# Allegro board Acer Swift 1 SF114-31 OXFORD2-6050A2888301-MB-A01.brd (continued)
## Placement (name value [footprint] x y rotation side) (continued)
CN2002  ACER_50505_0044N_002_4P  [FPC_ACES_4_100_R_150]  107.23 82.85 270 bottom
CN2003  ACER_50505_0044N_002_4P  [FPC_ACES_4_100_R_150]  50.1 156.25 180 bottom
CN2401  ALLTOP_C107MK_9093D_L_9P  [USB3_OTOP_9_DIP_RV_S_100_186]  6.8 113.2 90 bottom
CN2403  SUYIN_020173GR004M59GZL_4P  [USB_SYN_4_RS_S_110_250]  15 150.05 0 bottom
CN3000  ACES_50203_03001_001_30P  [WTB_ACES_30_050_SMD_R_F_265_1]  74.78 154.45 0 bottom
CN3150  CONCRAFT_099A4AC19HBLBNF_19P  [HDMI_CONFT_19_RS_060_218]  4.98 132.7 90 bottom
CN6000  HR_A1255WR_S_05PNLNT1TS1R_5P  [BTB_JOINT_5_125_M_215]  23.28 142.2 0 bottom
CN6050  ACES_50299_00901_001_9P  [HL10BM-6012B0131110-001]  93.32 19.9 180 bottom
CN9100  ACES_50503_0104N_001_10P  [FPC_ACES_10_100_R_200_3]  70.37 8.2 0 top
D250  SFI_SFI0402ML120C_LF_SMD_2P  [DS_100X050X060_2_S2]  114.7 150.11 90 bottom
D251  SFI_SFI0402ML120C_LF_SMD_2P  [DS_100X050X060_2_S2]  113.79 150.11 90 bottom
D252  SFI_SFI0402ML120C_LF_SMD_2P  [DS_100X050X060_2_S2]  112.87 150.11 90 bottom
D253  SFI_SFI0402ML120C_LF_SMD_2P  [DS_100X050X060_2_S2]  111.96 150.11 90 bottom
D254  SFI_SFI0402ML120C_LF_SMD_2P  [DS_100X050X060_2_S2]  111.05 150.11 90 bottom
D255  SFI_SFI0402ML120C_LF_SMD_2P  [DS_100X050X060_2_S2]  110.13 150.11 90 bottom
D256  SFI_SFI0402ML120C_LF_SMD_2P  [DS_100X050X060_2_S2]  109.22 150.11 90 bottom
D257  SFI_SFI0402ML120C_LF_SMD_2P  [DS_100X050X060_2_S2]  108.3 150.11 90 bottom
D280  LITEON_L30ESDXVC3_2_DSOT23_3P  [DSOT23_290X130X150_3_095]  111.86 61.75 0 bottom
D281  LITEON_L30ESDXVC3_2_DSOT23_3P  [DSOT23_290X130X150_3_095]  101.17 74.4 90 bottom
D282  SFI_SFI0402ML120C_LF_SMD_2P_DY  [DS_100X050X060_2_S2]  105 63.02 180 bottom
D500  LITEON_L30ESDXVC3_2_DSOT23_3P  [DSOT23_290X130X150_3_095]  30.5 28.04 180 bottom
D501  AMC_AZ2015_01H_SOD523_2P_DY  [DSSOD523_120X080X070_2_150]  12.82 55.32 270 bottom
D600  LITEON_L30ESDXVC3_2_DSOT23_3P_DY  [DSOT23_290X130X150_3_095]  6.96 73.02 0 bottom
D901  SFI_SFI0402ML120C_LF_SMD_2P_DY  [DS_100X050X060_2_S2]  19.22 24.36 90 bottom
D902  SFI_SFI0402ML120C_LF_SMD_2P_DY  [DS_100X050X060_2_S2]  23.16 22.58 90 bottom
D2406  AMAZING_AZ1045_04F_R7G_10P  [DS_250X100X065_10_050]  19.04 113 90 bottom
D2409  AMC_AZC099_04S_R7G_SOT23_6P  [DSSOT23_290X160X145_6_095]  18.97 109.14 0 bottom
D2410  AMC_AZC099_04S_R7G_SOT23_6P  [DSSOT23_290X160X145_6_095]  28.52 153.76 180 top
D3000  AMC_AZC099_04S_R7G_SOT23_6P  [DSSOT23_290X160X145_6_095]  81.58 140.94 0 bottom
D3950  SFI_SFI0402_050E050PP_LF_SMD_2P  [DS_100X050X060_2_S2]  100.99 33.88 270 top
D3951  SFI_SFI0402_050E050PP_LF_SMD_2P  [DS_100X050X060_2_S2]  111.14 32.41 0 bottom
D4500  SFI_SFI0603_240E2R5PP_LF_2P_DY  [DS_160X080X090_2]  85.67 101.83 90 bottom
D4501  DIODE-BAT54-TAP-PHP  [DSSOT23_292X130X109_3_095]  79.93 63.22 270 bottom
D4700  DIODE-BAT54-TAP-PHP  [DSSOT23_292X130X109_3_095]  67.81 162.76 0 top
D4701  DIODE-BAT54-TAP-PHP  [DSSOT23_292X130X109_3_095]  65.63 151.68 0 top
D6000  BAT54C_30V_0.2A  [TSMI_3B]  59.53 19.35 0 bottom
D6001  BAT54C_30V_0.2A  [TSMI_3B]  67.13 24 0 bottom
D7000  DIODE-BAT54-TAP-PHP  [DSSOT23_292X130X109_3_095]  93.01 147.04 270 bottom
D7152  SFI_SFI0402ML120C_LF_SMD_2P  [DS_100X050X060_2_S2]  14.83 137.29 270 top
D7200  BAT54_30V_0.2A_DY  [TSOT23_290X130X110_3_096_P1]  33.83 34.52 180 bottom
D7501  SFI0402_050E3R0PP_LF  [DS_100X050X060_2_S2]  69.29 149.45 270 top
D7503  SFI0402_050E3R0PP_LF  [DS_100X050X060_2_S2]  68.92 151.13 90 top
D9100  LITEON_L30ESDXVC3_2_DSOT23_3P  [DSOT23_290X130X150_3_095]  73.71 6.31 0 bottom
D9128  EVL_19_223_ S2T1D _C30_2T_4P  [LED_EVERLI_V_D_160X150X060]  43.2 7.75 180 bottom
D9129  EVL_19_223_ S2T1D _C30_2T_4P  [LED_EVERLI_V_D_160X150X060]  58.56 3.2 180 bottom
D9150  SFI_SFI0402ML120C_LF_SMD_2P_DY  [DS_100X050X060_2_S2]  51.06 2.52 180 top
D60000  DIODE-BAT54-TAP-PHP  [DSSOT23_292X130X109_3_095]  106.85 112.37 180 bottom
D60002  BAT54C_30V_0.2A  [TSMI_3B]  56.16 20.7 270 bottom
D60003  BAV99  [DSSOT23_290X130X110_3_095-2]  55.72 30.68 270 bottom
FIX1  -  [FIX_MASK]  15.16 143.18 0 top
FIX2  -  [FIX_MASK]  15.08 32.74 0 top
FIX3  -  [FIX_MASK]  105.2 18.29 0 top
FIX4  -  [FIX_MASK]  114.96 157.07 0 top
FIX5  -  [FIX_MASK]  15.16 143.18 180 bottom
FIX6  -  [FIX_MASK]  13.2 3.56 180 bottom
FIX7  -  [FIX_MASK]  105.58 18.16 180 bottom
FIX8  -  [FIX_MASK]  98.6 142.7 180 bottom
FIX23  -  [FIX_MASK]  53.03 151.03 180 bottom
FIX24  -  [FIX_MASK]  27.84 154.14 180 bottom
FIX25  -  [FIX_MASK]  52.14 157.17 0 top
FIX26  -  [FIX_MASK]  25.37 156.93 0 top
FIX9113  -  [FIX_MASK]  77.16 3.17 180 bottom
FIX9114  -  [FIX_MASK]  77.3 3.21 0 top
FIX9115  -  [FIX_MASK]  58.82 10.5 180 bottom
FIX9116  -  [FIX_MASK]  66.68 2.25 0 top
FUSE3004  1A_32V  [FUSE_160X080X031_2]  95.16 151.3 0 top
JACK600  SINGA_2SJ3095_078111F_6P  [AUDIO_SIGAT_6_R_165_165]  13.77 98.4 90 bottom
L300  FBM_11_160808_121T  [EMIS_BLM11]  65.58 162.41 270 top
L2404  MCF12102G900-T  [CAESAR-6014B0247601-001]  22 109.2 180 bottom
L2406  MCF12102G900-T  [CAESAR-6014B0247601-001]  31.94 154.05 180 top
L2432  WCM_2012SHS_850T  [LS_200X120X140_4_080]  22.83 111.81 180 bottom
L2440  WCM_2012SHS_850T  [LS_200X120X140_4_080]  22 113.72 180 bottom
L6000  PCMB061H_4R7MS  [LS_660X660X180_2_570]  78.99 27.28 270 bottom
L6100  PCMB061H-2R2MS  [LS_660X660X180_2_540]  72.18 133.58 270 bottom
L6150  PCMB061H-1R0MS  [LS_660X660X180_2_605]  92.38 133.58 270 bottom
L6610  PCMB061H-R33MS  [LS_660X660X180_4]  89.04 81.48 180 bottom
L6710  PCMB061H-R33MS  [LS_660X660X180_4]  80.95 46.66 90 bottom
L7600  KC_FBMA_11_321611_121A60T  [LS_320X160X130_2]  26.24 134.31 270 bottom
L7601  KC_FBMA_11_321611_121A60T  [LS_320X160X130_2]  73.15 26.82 270 bottom
L60300  PCMB061H-1R0MS  [LS_660X660X180_2_605]  48.49 30.08 90 bottom
L60600  NRS5020T1R0N  [LS_500X500X200_2_340_P2]  93.27 118.97 90 bottom
L60900  PCMB061H_R47MS  [LS_660X660X180_2_605]  90.52 109.12 270 bottom
NOREF  -  []  8.71 146.95 90 top
NOREF#2  -  []  50.01 153.44 0 top
NOREF#3  -  [unnamed#2]  2.37 73.75 90 top
NOREF#4  -  []  32.77 5.64 180 top
NOREF#5  -  []  7.71 10.85 90 top
NOREF#6  -  [unnamed#3]  13.47 90.75 90 top
NOREF#7  -  []  75.78 13.15 180 top
NOREF#8  -  []  106.22 91.49 270 top
NOREF#9  -  []  21.69 33.45 90 top
NOREF#10  -  []  99.56 160.95 90 top
NOREF#11  -  []  111.6 107.57 270 top
NOREF#12  -  []  116.97 77.79 90 top
NOREF#13  -  []  7.62 38.65 90 top
NOREF#14  -  []  43.57 156.67 0 top
NOREF#15  -  [unnamed#3]  59.37 7.25 90 top
NOREF#16  -  [unnamed#3]  118.77 5 90 top
NOREF#17  -  [unnamed#2]  0 151.75 90 top
NOREF#18  -  []  36.04 185.32 0 top
NOREF#19  -  []  61.1 149.95 270 top
NOREF#20  -  []  119.77 129.43 90 top
NOREF#21  -  []  119.77 101.43 90 top
NOREF#22  -  [unnamed#4]  80.32 10.26 90 top
NOREF#23  -  []  58.6 146.95 90 top
NOREF#24  -  [unnamed#5]  118.49 11.86 90 top
NOREF#25  -  [unnamed#4]  56.5 152.25 90 top
NOREF#26  -  []  38.82 13.15 90 top
NOREF#27  -  []  87.47 13.14 180 top
NOREF#28  -  []  119.77 29.87 90 top
NOREF#29  -  []  119.77 157.45 90 top
NOREF#30  -  [unnamed#3]  3 156.45 90 top
NOREF#31  -  [unnamed#3]  111.58 46.25 90 top
NOREF#32  -  []  37.54 161.75 180 top
NOREF#33  -  []  1.37 72.43 270 top
NOREF#34  -  []  3.62 56.1 270 top
NOREF#35  -  []  71.23 1.14 0 top
NOREF#36  -  []  119.77 57.79 90 top
NOREF#37  -  []  84.17 6.04 180 top
NOREF#38  -  [unnamed#3]  114.98 30.75 90 top
NOREF#39  -  []  -4.41 -5.85 0 top
NOREF#40  -  [unnamed#2]  83.18 6.05 270 top
NOREF#41  -  []  -1 157.01 90 top
NOREF#42  -  [unnamed#3]  0 164.25 90 top
NOREF#43  -  []  102.95 13.15 180 top
NOREF#44  -  [unnamed#3]  0 5 90 top
NOREF#45  -  [unnamed#5]  6.55 166.57 90 top
NOREF#46  -  []  58.62 161.75 90 top
NOREF#47  -  []  63.79 5.65 90 bottom
PAD319  POWERPAD1x1m  [POWERPAD1X1M]  65 160.22 90 top
PAD500  POWERPAD1x1m  [POWERPAD1X1M]  15.19 72.36 180 top
PAD501  POWERPAD1x1m  [POWERPAD1X1M]  7.26 51.63 90 bottom
PAD502  POWERPAD1x1m  [POWERPAD1X1M]  15.26 79.78 180 top
PAD503  POWERPAD1x1m  [POWERPAD1X1M]  12.16 41.66 180 bottom
PAD2000  -  [POWERPAD_2_0610]  106.5 101.96 270 bottom
PAD3003  POWERPAD1x1m  [POWERPAD1X1M]  60.5 141.55 0 bottom
PAD4501  POWERPAD2x2M_DY  [POWERPAD2X2M_NP]  82.29 65.02 180 top
PAD6100  -  [POWERPAD_2_0610]  77.26 127.74 270 bottom
PAD6110  -  [POWERPAD_2_0610]  68.35 143.18 90 bottom
PAD6121  POWERPAD1x1m  [POWERPAD1X1M]  77.64 141.2 0 bottom
PAD6150  -  [POWERPAD_2_0610]  95.17 127.86 270 bottom
PAD6160  -  [POWERPAD_2_0610]  86.53 143.99 0 bottom
PAD6610  -  [POWERPAD_2_0610]  101.01 78.13 0 bottom
PAD6710  -  [POWERPAD_2_0610]  89.38 38.79 270 bottom
PAD7101  -  [POWERPAD_2_0610]  68.5 125.83 180 bottom
PAD7102  -  [POWERPAD_2_0610]  87.32 123.67 0 bottom
PAD7103  POWERPAD1x1m  [POWERPAD1X1M]  88.31 128.63 180 bottom
PAD7104  -  [POWERPAD_2_0610]  61.01 125.83 0 bottom
PAD60300  -  [POWERPAD_2_0610]  40.08 35.05 90 bottom
PAD60310  -  [POWERPAD_2_0610]  46.91 20.21 0 bottom
PAD60350  POWERPAD1x1m  [POWERPAD1X1M]  42.11 20.45 270 bottom
PAD60351  POWERPAD1x1m  [POWERPAD1X1M]  33.35 24.87 90 bottom
PAD60610  -  [POWERPAD_2_0610]  94.66 124.43 270 bottom
PAD60900  -  [POWERPAD_2_0610]  102.79 103.1 270 bottom
PAD60910  -  [POWERPAD_2_0610]  94.79 110.44 0 bottom
PAD61000  POWERPAD1x1m  [POWERPAD1X1M]  100.12 125.2 90 bottom
PAD61110  POWERPAD1x1m  [POWERPAD1X1M]  102.79 122.28 90 bottom
PAD61700  POWERPAD1x1m  [POWERPAD1X1M]  105.33 115.42 0 bottom
Q281  PM513BA  [TSOT23_292X130X120_3_095]  106.65 61.98 270 bottom
Q300  L2N7002WT1G  [TSSOT323_200X125X100_3_065]  78.28 145.41 90 bottom
Q310  RU1C001UNTCL  [UMT3F_200X125X100_3_065]  101.14 157.33 90 top
Q311  RU1C001UNTCL  [UMT3F_200X125X100_3_065]  106.73 155.17 0 top
Q1300  FDC638APZ_DY  [TSOT_290X160X110_6_095]  55.17 125.07 0 bottom
Q1302  L2N7002DW1T1G  [TSSC88_200X125X110_6_065-2]  26.92 128.04 180 bottom
Q3000  PM513BA  [TSOT23_292X130X120_3_095]  57.71 142.09 90 bottom
Q3001  L2N7002DW1T1G  [TSSC88_200X125X110_6_065-2]  56.82 138.28 90 bottom
Q3003  L2N7002WT1G  [TSSOT323_200X125X100_3_065]  97.6 156.82 90 top
Q3004  PM513BA  [TSOT23_292X130X120_3_095]  94.55 154.03 90 top
Q3006  LMBT3904LT1G  [TSSOT23_292X130X111_3_096]  59.99 133.71 0 bottom
Q3007  L2N7002WT1G  [TSSOT323_200X125X100_3_065]  61.57 130.61 90 bottom
Q3150  RU1C001UNTCL  [UMT3F_200X125X100_3_065]  18.92 125.02 180 bottom
Q3151  RU1C001UNTCL  [UMT3F_200X125X100_3_065]  21.36 125.02 180 bottom
Q3152  L2N7002WT1G  [TSSOT323_200X125X100_3_065]  19.25 128.22 270 bottom
Q3153  L2N7002WT1G  [TSSOT323_200X125X100_3_065]  23.75 125.22 0 bottom
Q3500  RU1C001UNTCL_DY  [UMT3F_200X125X100_3_065]  105.33 130.4 90 bottom
Q3501  RU1C001UNTCL_DY  [UMT3F_200X125X100_3_065]  112.7 130.91 270 bottom
Q3502  L2N7002WT1G_DY  [TSSOT323_200X125X100_3_065]  110.03 131.29 0 bottom
Q4505  L2N7002WT1G_DY  [TSSOT323_200X125X100_3_065]  73.86 110.26 90 bottom
Q4506  L2N7002DW1T1G  [TSSC88_200X125X110_6_065-2]  82.09 131.67 0 bottom
Q4513  RU1C001UNTCL  [UMT3F_200X125X100_3_065]  101.41 45.91 180 bottom
Q4516  RU1C001UNTCL  [UMT3F_200X125X100_3_065]  112.9 108.1 0 bottom
Q4517  RU1C001UNTCL  [UMT3F_200X125X100_3_065]  111.96 103.63 90 bottom
Q4524  L2N7002WT1G  [TSSOT323_200X125X100_3_065]  115.31 107.9 0 bottom
Q4525  L2N7002WT1G  [TSSOT323_200X125X100_3_065]  114.55 103.66 0 bottom
Q4714  L2N7002WT1G  [TSSOT323_200X125X100_3_065]  111.6 112.45 0 bottom
Q6000  AON7934  [TSMOS_300X300X080_8_065_T4]  73.63 30.83 180 bottom
Q6010  RQ3E100BNFU7TB  [MOSFET_300X300X112_8_065]  53.44 17.39 90 top
Q6011  RQ3E070BNFU7TB  [MOSFET_300X300X112_8_065]  58.55 17.47 270 top
Q6012  RQ3E100BNFU7TB  [MOSFET_300X300X112_8_065]  87.2 33.02 180 bottom
Q6610  FAIRCHILD_FDMS3669S  [TSMOS_500X600X110_8_127_T1]  96.35 82.04 180 bottom
Q6710  FAIR_FDMS3664S_8P  [TSMOS_500X600X110_8_127_T1]  87.13 44.21 180 bottom
Q7000  L2N7002WT1G  [TSSOT323_200X125X100_3_065]  96.06 147.04 180 bottom
Q7106  L2N7002WT1G  [TSSOT323_200X125X100_3_065]  115.26 117.73 270 bottom
Q7108  L2N7002WT1G  [TSSOT323_200X125X100_3_065]  115.26 115.19 270 bottom
Q7114  L2N7002WT1G  [TSSOT323_200X125X100_3_065]  113.97 112.45 0 bottom
Q7120  L2N7002WT1G  [TSSOT323_200X125X100_3_065]  98.85 147.04 180 bottom
Q7202  PM513BA  [TSOT23_292X130X120_3_095]  35.76 38.61 0 bottom
Q7214  L2N7002DW1T1G  [TSSC88_200X125X110_6_065-2]  65.12 34.66 90 bottom
Q60002  L2N7002DW1T1G  [TSSC88_200X125X110_6_065-2]  54.07 23.9 0 bottom
Q60003  L2N7002DW1T1G  [TSSC88_200X125X110_6_065-2]  54.9 27.88 270 bottom
R20  100K_5%_2  [RSC_100X050X040_2]  113.92 152.24 270 top
R28  200_5%_2  [RSC_100X050X040_2]  113.56 110.39 0 bottom
R29  200_5%_2  [RSC_100X050X040_2]  112.95 115.93 270 bottom
R35  10K_5%_2  [RSC_100X050X040_2]  76.12 42.62 90 bottom
R281  0_5%_2_DY  [RSC_100X050X040_2]  110.46 59.03 90 bottom
R282  0_5%_2_DY  [RSC_100X050X040_2]  113.23 59.03 90 bottom
R283  0_5%_2  [RSC_100X050X040_2]  111.4 59.03 90 bottom
R284  0_5%_2  [RSC_100X050X040_2]  112.32 59.03 90 bottom
R285  0_5%_2  [RSC_100X050X040_2]  101.62 70.76 90 bottom
R286  0_5%_2_DY  [RSC_100X050X040_2]  101.27 72.03 0 bottom
R301  10K_5%_2  [RSC_100X050X040_2]  108.55 157.3 0 top
R308  47K_5%_2  [RSC_100X050X040_2]  88.9 148.31 180 top
R309  47K_5%_2  [RSC_100X050X040_2]  88.9 149.2 180 top
R310  1K_5%_2  [RSC_100X050X040_2]  103.31 157.95 0 top
R311  10K_5%_2  [RSC_100X050X040_2]  107.24 152.37 270 top
R312  0_5%_2_DY  [RSC_100X050X040_2]  106.35 152.37 270 top
R313  0_5%_2_DY  [RSC_100X050X040_2]  89.33 150.47 270 top
R314  0_5%_2_DY  [RSC_100X050X040_2]  90.6 151.1 0 top
R316  1.8K_5%_2  [RSC_100X050X040_2]  87.42 164.34 180 top
R317  1.8K_5%_2  [RSC_100X050X040_2]  87.42 165.23 180 top
R318  2.2_5%_3  [RSC_160X080X080_2]  66.51 156.97 0 top
R320  100K_5%_2  [RSC_100X050X040_2]  108.55 158.2 180 top
R321  3.3K_5%_2  [RSC_100X050X040_2]  86.92 149.2 0 top
R322  3.3K_5%_2  [RSC_100X050X040_2]  86.92 148.31 0 top
R323  10K_5%_2  [RSC_100X050X040_2]  108.33 156.03 90 top
R324  100K_5%_2  [RSC_100X050X040_2]  78.38 147.04 180 bottom
R325  0_5%_2_DY  [RSC_100X050X040_2]  84.05 146.3 180 top
R332  10K_5%_2_DY  [RSC_100X050X040_2]  67.13 158.47 0 top
R333  100K_5%_2  [RSC_100X050X040_2]  81.96 144.65 180 top
R334  10K_5%_2  [RSC_100X050X040_2]  64.88 157.57 90 top
R340  33_5%_2  [RSC_100X050X040_2]  73.12 41.33 0 bottom
R341  33_5%_2  [RSC_100X050X040_2]  72.41 52.27 90 bottom
R342  33_5%_2  [RSC_100X050X040_2]  71.78 38.66 180 bottom
R343  33_5%_2  [RSC_100X050X040_2]  71.78 37.74 180 bottom
R346  100K_5%_2  [RSC_100X050X040_2]  65.17 164.39 270 top
R350  10K_5%_2  [RSC_100X050X040_2]  78.48 144.07 270 top
R351  18.7K_1%_2  [RSC_100X050X040_2]  65.27 151.18 0 bottom
R352  100K_1%_NTC  [RSC_100X050X055_2]  64.92 149.91 270 bottom
R390  10K_5%_2  [RSC_100X050X040_2]  68.46 152.74 180 top
R391  10K_5%_2_DY  [RSC_100X050X040_2]  68.01 151.13 90 top
R500  short_0603_25  [RSC_160X080X080_2_25_SHORT]  8.61 57.91 270 bottom
R501  20K_1%_2_DY  [RSC_100X050X040_2]  14.81 57.51 90 top
R502  200K_5%_2  [RSC_100X050X040_2]  16.58 57.51 90 top
R503  1K_5%_2_DY  [RSC_100X050X040_2]  18.36 55.6 270 top
R504  100K_5%_2  [RSC_100X050X040_2]  15.69 57.51 90 top
R505  1K_5%_2  [RSC_100X050X040_2]  19.05 57.23 270 top
R506  0_5%_2  [RSC_100X050X040_2]  17.52 51.59 0 top
R507  75_5%_2  [RSC_100X050X040_2]  17.52 53.36 0 top
R508  0_5%_3  [RSC_160X080X055_2]  17.83 43.54 90 bottom
R509  0_5%_3  [RSC_160X080X055_2]  16.68 43.54 90 bottom
R510  0_5%_3  [RSC_160X080X055_2]  14.4 43.54 90 bottom
R511  0_5%_3  [RSC_160X080X055_2]  15.54 43.54 90 bottom
R512  100_5%_2  [RSC_100X050X040_2]  17.09 50.57 180 top
R513  short_0603_25  [RSC_160X080X080_2_25_SHORT]  15.41 49.63 180 bottom
R514  short_0402_15  [RSC_100X050X040_2_15_SHORT]  16.68 59.66 0 top
R515  1K_5%_2  [RSC_100X050X040_2]  19.05 58.83 90 top
R520  short_0402_5  [RSC_100X050X040_2_SHORT]  19.05 60.43 90 top
R521  short_0402_5  [RSC_100X050X040_2_SHORT]  20.09 53.85 270 top
R531  100K_5%_2  [RSC_100X050X040_2]  9.7 58.39 90 top
R600  2.2K_5%_2  [RSC_100X050X040_2]  14.96 85.98 180 bottom
R601  2.2K_5%_2  [RSC_100X050X040_2]  7.16 83.79 0 bottom
R602  0_5%_2  [RSC_100X050X040_2]  14.96 86.87 0 bottom
R603  0_5%_2  [RSC_100X050X040_2]  5.51 83.79 0 bottom
R604  22_5%_2  [RSC_100X050X040_2]  6.12 80.85 90 bottom
R605  22_5%_2  [RSC_100X050X040_2]  7.26 80.87 90 bottom
R606  4.7K_5%_2  [RSC_100X050X040_2]  8.18 80.87 90 bottom
R607  4.7K_5%_2  [RSC_100X050X040_2]  5.2 80.85 90 bottom
R610  0_5%_2_DY  [RSC_100X050X040_2]  6.19 90.55 0 bottom
R704  short_0402_15  [RSC_100X050X040_2_15_SHORT]  80.82 67.67 0 top
R900  6.2K_1%_2  [RSC_100X050X040_2]  15.08 19.68 270 bottom
R901  0_5%_2  [RSC_100X050X040_2]  20.87 13.9 0 bottom
R1301  0_5%_5  [RSC_200X125X115_2]  55.93 128.75 0 bottom
R1302  0_5%_2_DY  [RSC_100X050X040_2]  39.93 132.18 180 top
R1306  0_5%_2  [RSC_100X050X040_2]  39.93 133.07 0 top
R1307  10K_5%_2  [RSC_100X050X040_2]  27.35 130.02 180 bottom
R2000  RSC_0402_DY  [RSC_100X050X040_2]  116.23 98.83 0 bottom
R2001  10K_5%_2  [RSC_100X050X040_2]  112.01 101.93 180 bottom
R2410  10K_5%_2  [RSC_100X050X040_2]  18.39 120.93 270 bottom
R3000  47K_5%_2  [RSC_100X050X040_2]  55.29 140.82 0 bottom
R3001  470K_5%_2  [RSC_100X050X040_2]  55.8 139.93 0 bottom
R3004  100_5%_2  [RSC_100X050X040_2]  57.45 139.93 180 bottom
R3005  short_0603_10  [RSC_160X080X080_2_SHORT]  81.07 136.83 90 bottom
R3006  47K_5%_2  [RSC_100X050X040_2]  60.63 128.63 90 bottom
R3007  4.7K_5%_2  [RSC_100X050X040_2]  61.52 128.63 90 bottom
R3010  100K_5%_2  [RSC_100X050X040_2]  58.85 138.66 90 bottom
R3011  100_5%_2  [RSC_100X050X040_2]  83.64 140.23 90 bottom
R3013  100_5%_2  [RSC_100X050X040_2]  112.9 152.25 270 top
R3016  100K_5%_2  [RSC_100X050X040_2]  70.66 149.07 90 bottom
R3017  100K_5%_2  [RSC_100X050X040_2]  67.61 149.28 180 bottom
R3020  10K_5%_2  [RSC_100X050X040_2]  104.01 156.15 90 top
R3021  100K_5%_2  [RSC_100X050X040_2]  98.35 155.22 0 top
R3025  2.2K_5%_2  [RSC_100X050X040_2]  58.9 136.14 270 bottom
R3029  short_0603_10  [RSC_160X080X080_2_SHORT]  82.27 136.83 90 bottom
R3030  100K_5%_2  [RSC_100X050X040_2]  100.9 151.13 180 top
R3060  150_5%_2_DY  [RSC_100X050X040_2]  71.57 149.07 270 bottom
R3061  0_5%_2  [RSC_100X050X040_2]  70.3 150.98 0 bottom
R3068  0_5%_3  [RSC_160X080X055_2]  99.39 153.21 180 top
R3069  0_5%_3_DY  [RSC_160X080X055_2]  101.97 152.47 180 top
R3150  100K_5%_2  [RSC_100X050X040_2]  16.66 140.08 90 top
R3152  2.2K_5%_2  [RSC_100X050X040_2]  16.2 138.45 90 top
R3153  2.2K_5%_2  [RSC_100X050X040_2]  16.2 136.83 270 top
R3154  1K_5%_2  [RSC_100X050X040_2]  14.83 139.09 270 top
R3157  619_1%_2  [RSC_100X050X040_2]  18.11 125.81 270 top
R3158  619_1%_2  [RSC_100X050X040_2]  18.11 127.43 90 top
R3159  619_1%_2  [RSC_100X050X040_2]  19.02 128.57 270 top
R3160  619_1%_2  [RSC_100X050X040_2]  19.02 130.2 90 top
R3161  619_1%_2  [RSC_100X050X040_2]  18.11 131.34 270 top
R3162  619_1%_2  [RSC_100X050X040_2]  18.11 132.97 90 top
R3163  619_1%_2  [RSC_100X050X040_2]  19 135.71 90 top
R3164  619_1%_2  [RSC_100X050X040_2]  19 134.09 270 top
R3167  120_1%_2  [RSC_100X050X040_2]  14.83 126.62 270 top
R3168  120_1%_2  [RSC_100X050X040_2]  15.77 129.39 270 top
R3169  120_1%_2  [RSC_100X050X040_2]  14.86 132.16 270 top
R3170  120_1%_2  [RSC_100X050X040_2]  15.74 134.9 270 top
R3171  10K_5%_2  [RSC_100X050X040_2]  24 123.16 0 bottom
R3178  2.2K_5%_2  [RSC_100X050X040_2]  21.26 123.16 180 bottom
R3179  2.2K_5%_2  [RSC_100X050X040_2]  18.92 123.16 180 bottom
R3180  short_0603_25  [RSC_160X080X080_2_25_SHORT]  16.46 126.06 180 top
R3181  short_0603_25  [RSC_160X080X080_2_25_SHORT]  16.46 127.18 180 top
R3182  short_0603_25  [RSC_160X080X080_2_25_SHORT]  17.4 128.83 180 top
R3183  short_0603_25  [RSC_160X080X080_2_25_SHORT]  17.4 129.95 180 top
R3184  short_0603_25  [RSC_160X080X080_2_25_SHORT]  16.48 131.6 180 top
R3185  short_0603_25  [RSC_160X080X080_2_25_SHORT]  16.48 132.71 180 top
R3186  short_0603_25  [RSC_160X080X080_2_25_SHORT]  17.37 134.34 180 top
R3187  short_0603_25  [RSC_160X080X080_2_25_SHORT]  17.37 135.46 180 top
R3503  0_5%_2_DY  [RSC_100X050X040_2]  105.84 121.51 0 bottom
R3504  0_5%_2_DY  [RSC_100X050X040_2]  105.84 123.8 0 bottom
R3505  0_5%_2_DY  [RSC_100X050X040_2]  105.84 125.96 0 bottom
R3506  0_5%_2_DY  [RSC_100X050X040_2]  105.84 127.74 0 bottom
R3507  0_5%_2_DY  [RSC_100X050X040_2]  105.84 125.07 0 bottom
R3509  0_5%_2_DY  [RSC_100X050X040_2]  109.47 118.72 90 bottom
R3510  0_5%_2_DY  [RSC_100X050X040_2]  105.84 120.62 0 bottom
R3511  10K_5%_2_DY  [RSC_100X050X040_2]  105.84 128.63 180 bottom
R3513  10K_5%_2_DY  [RSC_100X050X040_2]  105.84 119.74 180 bottom
R3514  10K_5%_2_DY  [RSC_100X050X040_2]  112.19 132.56 180 bottom
R3515  10K_5%_2_DY  [RSC_100X050X040_2]  108.38 132.05 270 bottom
R3516  2.2K_5%_2_DY  [RSC_100X050X040_2]  108.38 130.4 270 bottom
R3950  0_5%_2_DY  [RSC_100X050X040_2]  101.29 42.16 180 top
R3955  0_5%_2  [RSC_100X050X040_2]  103.48 41.81 90 top
R3962  0_5%_2  [RSC_100X050X040_2]  95.04 37.13 0 top
R3963  10K_5%_2_DY  [RSC_100X050X040_2]  102.56 41.81 270 top
R3964  0_5%_3  [RSC_160X080X055_2]  111.73 35.81 90 bottom
R3965  10K_5%_2_DY  [RSC_100X050X040_2]  100.94 40.77 90 top
R3966  0_5%_3  [RSC_160X080X055_2]  97.33 43.36 180 bottom
R4100  243_1%_2  [RSC_100X050X040_2]  70.16 113.41 90 bottom
R4101  243_1%_2  [RSC_100X050X040_2]  52.95 117.79 0 top
R4102  243_1%_2  [RSC_100X050X040_2]  24.86 93.03 0 bottom
R4103  243_1%_2  [RSC_100X050X040_2]  31.73 108.58 180 bottom
R4104  4.7K_1%_2  [RSC_100X050X040_2]  67.63 117.13 270 top
R4105  4.7K_1%_2  [RSC_100X050X040_2]  68.13 115.82 180 top
R4106  243_1%_2  [RSC_100X050X040_2]  70.16 111.76 270 bottom
R4107  243_1%_2  [RSC_100X050X040_2]  52.95 118.68 0 top
R4108  243_1%_2  [RSC_100X050X040_2]  24.86 93.92 0 bottom
R4109  243_1%_2  [RSC_100X050X040_2]  33.33 108.58 0 bottom
R4110  4.7K_1%_2  [RSC_100X050X040_2]  70.2 115.81 180 top
R4111  4.7K_1%_2  [RSC_100X050X040_2]  70.2 117.59 0 top
R4112  0_5%_2_DY  [RSC_100X050X040_2]  70.2 118.47 0 top
R4113  0_5%_2_DY  [RSC_100X050X040_2]  68.58 118.5 180 top
R4114  80.6_1%_2  [RSC_100X050X040_2]  48.29 96.92 0 top
R4115  80.6_1%_2  [RSC_100X050X040_2]  48.3 97.86 0 top
R4116  80.6_1%_2  [RSC_100X050X040_2]  47.57 103.34 0 top
R4117  80.6_1%_2  [RSC_100X050X040_2]  46.32 104.33 90 top
R4118  80.6_1%_2  [RSC_100X050X040_2]  48.59 102.27 0 top
R4119  80.6_1%_2  [RSC_100X050X040_2]  42.75 100.66 0 top
R4120  80.6_1%_2  [RSC_100X050X040_2]  47.14 100.83 270 top
R4121  80.6_1%_2  [RSC_100X050X040_2]  42.67 101.61 0 top
R4122  80.6_1%_2  [RSC_100X050X040_2]  44.06 97.89 0 top
R4123  80.6_1%_2  [RSC_100X050X040_2]  42.87 105.86 90 top
R4124  80.6_1%_2  [RSC_100X050X040_2]  44.16 105.78 90 top
R4125  80.6_1%_2  [RSC_100X050X040_2]  41.72 103.8 90 top
R4126  80.6_1%_2  [RSC_100X050X040_2]  44.2 108.31 180 top
R4127  80.6_1%_2  [RSC_100X050X040_2]  39.27 106.74 0 top
R4128  80.6_1%_2  [RSC_100X050X040_2]  41.06 106.65 90 top
R4129  80.6_1%_2  [RSC_100X050X040_2]  40.88 109.55 270 top
R4130  80.6_1%_2  [RSC_100X050X040_2]  38.68 107.63 0 top
R4131  80.6_1%_2  [RSC_100X050X040_2]  38.91 108.54 0 top
R4132  80.6_1%_2  [RSC_100X050X040_2]  36.9 111.38 270 top
R4133  80.6_1%_2  [RSC_100X050X040_2]  38.55 111.51 270 top
R4134  80.6_1%_2  [RSC_100X050X040_2]  37.66 109.26 90 top
R4135  80.6_1%_2  [RSC_100X050X040_2]  39.61 109.89 180 top
R4136  80.6_1%_2  [RSC_100X050X040_2]  42.08 107.84 90 top
R4137  80.6_1%_2  [RSC_100X050X040_2]  42.05 109.54 90 top
R4138  80.6_1%_2  [RSC_100X050X040_2]  46.13 100.96 270 top
R4139  80.6_1%_2  [RSC_100X050X040_2]  35.89 109.84 0 top
R4140  80.6_1%_2  [RSC_100X050X040_2]  39.59 111.15 270 top
R4141  80.6_1%_2  [RSC_100X050X040_2]  45.28 103.72 90 top
R4142  80.6_1%_2  [RSC_100X050X040_2]  43.28 99.68 0 top
R4143  80.6_1%_2  [RSC_100X050X040_2]  44.04 98.79 0 top
R4144  243_1%_2  [RSC_100X050X040_2]  42.61 47.67 270 bottom
R4145  80.6_1%_2  [RSC_100X050X040_2]  40.9 55.98 90 top
R4146  80.6_1%_2  [RSC_100X050X040_2]  45.5 58.14 270 top
R4147  80.6_1%_2  [RSC_100X050X040_2]  40.14 57.4 0 top
R4148  80.6_1%_2  [RSC_100X050X040_2]  41.56 59.56 90 top
R4149  80.6_1%_2  [RSC_100X050X040_2]  43.94 58.39 180 top
R4150  80.6_1%_2  [RSC_100X050X040_2]  43.92 59.33 0 top
R4151  243_1%_2  [RSC_100X050X040_2]  42.6 49.27 90 bottom
R4152  80.6_1%_2  [RSC_100X050X040_2]  43.8 60.83 0 top
R4153  80.6_1%_2  [RSC_100X050X040_2]  39.63 55.27 0 top
R4154  80.6_1%_2  [RSC_100X050X040_2]  36.91 54.23 0 top
R4155  80.6_1%_2  [RSC_100X050X040_2]  43.35 56.97 0 top
R4156  80.6_1%_2  [RSC_100X050X040_2]  41.33 53.82 270 top
R4157  80.6_1%_2  [RSC_100X050X040_2]  36.91 53.31 0 top
R4158  80.6_1%_2  [RSC_100X050X040_2]  38.49 52.65 270 top
R4159  80.6_1%_2  [RSC_100X050X040_2]  38.01 51.28 0 top
R4160  80.6_1%_2  [RSC_100X050X040_2]  35.64 52.4 0 top
R4161  80.6_1%_2  [RSC_100X050X040_2]  37.35 50.36 0 top
R4162  80.6_1%_2  [RSC_100X050X040_2]  34.72 49.13 0 top
R4163  80.6_1%_2  [RSC_100X050X040_2]  35.39 50.03 0 top
R4164  80.6_1%_2  [RSC_100X050X040_2]  34.15 48.1 0 top
R4165  80.6_1%_2  [RSC_100X050X040_2]  38.31 47.65 90 top
R4166  80.6_1%_2  [RSC_100X050X040_2]  39.45 53.23 270 top
R4167  80.6_1%_2  [RSC_100X050X040_2]  37.35 49.45 0 top
R4168  80.6_1%_2  [RSC_100X050X040_2]  41.81 56.87 90 top
R4169  80.6_1%_2  [RSC_100X050X040_2]  34.93 51.43 0 top
R4170  80.6_1%_2  [RSC_100X050X040_2]  36.84 48.31 0 top
R4171  80.6_1%_2  [RSC_100X050X040_2]  44.6 57.07 270 top
R4172  4.7K_1%_2  [RSC_100X050X040_2]  47.65 40.23 180 top
R4173  0_5%_2_DY  [RSC_100X050X040_2]  59.69 42.93 180 top
R4174  4.7K_1%_2  [RSC_100X050X040_2]  47.65 41.12 0 top
R4175  4.7K_1%_2  [RSC_100X050X040_2]  67.15 49.77 270 top
R4176  0_5%_2_DY  [RSC_100X050X040_2]  68.04 49.77 90 top
R4177  4.7K_1%_2  [RSC_100X050X040_2]  68.04 52.79 180 top
R4178  243_1%_2  [RSC_100X050X040_2]  58 41.6 90 bottom
R4179  243_1%_2  [RSC_100X050X040_2]  58.89 41.6 90 bottom
R4180  243_1%_2  [RSC_100X050X040_2]  31.55 81.02 180 bottom
R4181  243_1%_2  [RSC_100X050X040_2]  33.21 81.02 0 bottom
R4182  243_1%_2  [RSC_100X050X040_2]  24.89 65.07 0 bottom
R4183  80.6_1%_2  [RSC_100X050X040_2]  44.59 62.3 180 top
R4184  80.6_1%_2  [RSC_100X050X040_2]  42.53 60.22 90 top
R4185  80.6_1%_2  [RSC_100X050X040_2]  44.92 65.73 90 top
R4186  80.6_1%_2  [RSC_100X050X040_2]  44 65.73 90 top
R4187  243_1%_2  [RSC_100X050X040_2]  24.89 65.99 0 bottom
R4441  150K_5%_2  [RSC_100X050X040_2]  76.63 114.12 90 bottom
R4442  53.6K_1%_2  [RSC_100X050X040_2]  78.74 114.99 180 bottom
R4443  32.4K_1%_2  [RSC_100X050X040_2]  79.17 113.72 270 bottom
R4444  100K_1%_NTC  [RSC_100X050X055_2]  80.44 113.36 0 bottom
R4445  100K_5%_2  [RSC_100X050X040_2]  77.77 105.21 90 bottom
R4446  10K_5%_2  [RSC_100X050X040_2]  79.07 105.21 90 bottom
R4448  short_0402_5  [RSC_100X050X040_2_SHORT]  80.9 109.52 90 bottom
R4449  620K_5%_2  [RSC_100X050X040_2]  75.74 114.12 270 bottom
R4504  182_1%_2  [RSC_100X050X040_2]  57.14 81.16 0 top
R4505  182_1%_2  [RSC_100X050X040_2]  58.77 81.16 180 top
R4514  402_1%_2  [RSC_100X050X040_2]  74.61 85.21 0 top
R4518  402_1%_2  [RSC_100X050X040_2]  76.5 91.41 270 top
R4520  100K_5%_2  [RSC_100X050X040_2]  71.68 97.71 270 bottom
R4521  100_1%_2  [RSC_100X050X040_2]  72.51 74.14 180 top
R4522  402_1%_2  [RSC_100X050X040_2]  75.66 81.36 0 top
R4523  10K_5%_2  [RSC_100X050X040_2]  61.8 73.28 90 top
R4532  402_1%_2  [RSC_100X050X040_2]  72.25 84.37 180 top
R4533  10K_5%_2  [RSC_100X050X040_2]  68.81 95.6 180 top
R4534  10K_5%_2  [RSC_100X050X040_2]  70.35 63.6 270 bottom
R4536  75_5%_2  [RSC_100X050X040_2]  64.97 68.58 270 top
R4537  75_5%_2  [RSC_100X050X040_2]  65.86 68.58 270 top
R4538  75_5%_2  [RSC_100X050X040_2]  67.97 68 270 top
R4539  75_5%_2  [RSC_100X050X040_2]  63.21 65.64 270 top
R4540  short_0402_5  [RSC_100X050X040_2_SHORT]  64.74 63.63 270 bottom
R4541  49.9_1%_2  [RSC_100X050X040_2]  75 79.58 180 top
R4542  2.49K_1%_2  [RSC_100X050X040_2]  73.38 80.49 180 top
R4543  200K_5%_2  [RSC_100X050X040_2]  86.08 74.98 270 bottom
R4544  4.7K_5%_2  [RSC_100X050X040_2]  67.21 97.59 90 bottom
R4545  10K_5%_2  [RSC_100X050X040_2]  76.12 47.5 90 bottom
R4546  10K_5%_2  [RSC_100X050X040_2]  76.12 44.22 270 bottom
R4547  10K_5%_2  [RSC_100X050X040_2]  68.7 104.19 270 top
R4548  4.7K_5%_2  [RSC_100X050X040_2]  72.77 105.41 0 bottom
R4549  100K_5%_2  [RSC_100X050X040_2]  70.66 106.68 270 bottom
R4550  100K_5%_2  [RSC_100X050X040_2]  71.9 106.32 0 bottom
R4551  4.7K_5%_2  [RSC_100X050X040_2]  68.09 97.59 90 bottom
R4553  1K_5%_2  [RSC_100X050X040_2]  69.95 103.23 180 top
R4554  10K_1%_2_DY  [RSC_100X050X040_2]  69.95 104.11 180 top
R4555  100_1%_2  [RSC_100X050X040_2]  65.15 86.25 180 top
R4560  2.2K_5%_2  [RSC_100X050X040_2]  104.54 51.26 270 bottom
R4561  2.2K_5%_2_DY  [RSC_100X050X040_2]  107.99 51.33 270 bottom
R4562  2.2K_5%_2_DY  [RSC_100X050X040_2]  107.97 48.89 90 bottom
R4563  402_1%_2  [RSC_100X050X040_2]  75.05 83.18 0 top
R4564  113_1%_3  [RSC_160X080X055_2]  76.25 97.38 180 bottom
R4571  22_5%_2  [RSC_100X050X040_2]  78.43 52.65 180 bottom
R4572  22_5%_2  [RSC_100X050X040_2]  76.81 51.03 0 bottom
R4573  0_5%_2_DY  [RSC_100X050X040_2]  78.08 51.38 270 bottom
R4574  100_1%_2  [RSC_100X050X040_2]  70.96 68.38 270 top
R4575  20K_5%_2  [RSC_100X050X040_2]  71.35 107.95 0 bottom
R4576  0_5%_2  [RSC_100X050X040_2]  71.35 108.86 180 bottom
R4578  0_5%_3_DY  [RSC_160X080X055_2]  73.48 108.51 180 bottom
R4579  10M_5%_2  [RSC_100X050X040_2]  86.18 71.3 180 bottom
R4580  20K_5%_2  [RSC_100X050X040_2]  78.25 71.73 180 top
R4581  20K_5%_2  [RSC_100X050X040_2]  77.01 72.08 270 top
R4582  10K_5%_2_DY  [RSC_100X050X040_2]  104.98 52.58 0 bottom
R4583  2.2K_5%_2  [RSC_100X050X040_2]  104.54 48.56 90 bottom
R4584  4.7K_5%_2  [RSC_100X050X040_2]  29.59 122.73 90 bottom
R4586  10K_5%_2  [RSC_100X050X040_2]  82.6 129.06 0 bottom
R4587  1K_5%_2  [RSC_100X050X040_2]  84.81 130.89 0 bottom
R4590  200_1%_2  [RSC_100X050X040_2]  74.29 100.91 90 bottom
R4591  0_5%_2_DY  [RSC_100X050X040_2]  108.88 51.33 270 bottom
R4592  200_1%_2  [RSC_100X050X040_2]  76.22 100.33 0 top
R4593  0_5%_2_DY  [RSC_100X050X040_2]  108.86 48.89 90 bottom
R4596  200_1%_2  [RSC_100X050X040_2]  76.22 100.58 0 bottom
R4601  0_5%_2  [RSC_100X050X040_2]  74.85 103.45 0 top
R4602  301_1%_2  [RSC_100X050X040_2]  74.98 102.34 180 top
R4604  0_5%_2  [RSC_100X050X040_2]  74.85 103.45 0 bottom
R4605  301_1%_2  [RSC_100X050X040_2]  74.85 102.54 180 bottom
R4614  0_5%_2  [RSC_100X050X040_2]  76.22 101.24 0 top
R4617  100_1%_2  [RSC_100X050X040_2]  68.98 99.64 270 bottom
R4618  100_1%_2  [RSC_100X050X040_2]  69.87 99.64 270 bottom
R4619  100_1%_2  [RSC_100X050X040_2]  68.98 97.59 90 bottom
R4620  100_1%_2  [RSC_100X050X040_2]  69.87 97.59 90 bottom
R4621  short_0402_5  [RSC_100X050X040_2_SHORT]  81.48 69.27 270 bottom
R4622  short_0402_5  [RSC_100X050X040_2_SHORT]  80.57 69.27 270 bottom
R4623  short_0402_5  [RSC_100X050X040_2_SHORT]  66.66 81.75 180 top
R4625  2.7K_5%_2  [RSC_100X050X040_2]  65.83 63.32 90 bottom
R4628  1K_5%_2  [RSC_100X050X040_2]  28.19 125.75 180 bottom
R4631  10_5%_2  [RSC_100X050X040_2]  71.52 40.51 0 bottom
R4632  8.2K_5%_2  [RSC_100X050X040_2]  59.56 67.03 180 top
R4633  10_5%_2  [RSC_100X050X040_2]  71.52 52.27 90 bottom
R4635  short_0402_5  [RSC_100X050X040_2_SHORT]  69.08 62.86 270 bottom
R4637  0_5%_2_DY  [RSC_100X050X040_2]  99.67 45.36 90 bottom
R4639  10K_5%_2  [RSC_100X050X040_2]  112.57 105.38 0 bottom
R4640  10K_5%_2  [RSC_100X050X040_2]  28.65 128.57 270 bottom
R4641  2.2K_5%_2  [RSC_100X050X040_2]  116.18 102.87 270 bottom
R4642  10K_5%_2  [RSC_100X050X040_2]  113.2 106.27 0 bottom
R4643  10K_5%_2  [RSC_100X050X040_2]  25.27 127.63 90 bottom
R4644  2.2K_5%_2  [RSC_100X050X040_2]  116.93 106.99 90 bottom
R4645  200_1%_2  [RSC_100X050X040_2]  74.09 100.99 180 top
R4647  0_5%_2  [RSC_100X050X040_2]  76.22 101.5 0 bottom
R4648  10_5%_2  [RSC_100X050X040_2]  71.52 41.73 180 bottom
R4649  10K_5%_2  [RSC_100X050X040_2]  109.98 152.19 180 top
R4652  10K_5%_2  [RSC_100X050X040_2]  99.67 47.01 90 bottom
R4653  10K_5%_2  [RSC_100X050X040_2]  63.9 156.74 270 top
R4655  10K_5%_2  [RSC_100X050X040_2]  101.39 44.04 0 bottom
R4656  10K_5%_2  [RSC_100X050X040_2]  110.99 118.06 0 bottom
R4657  10K_5%_2  [RSC_100X050X040_2]  69.95 105 180 top
R4659  20K_5%_2  [RSC_100X050X040_2]  63.74 154.24 90 top
R4660  10K_5%_2  [RSC_100X050X040_2]  76.25 52.3 90 bottom
R4661  10K_5%_2_DY  [RSC_100X050X040_2]  29.59 125.35 270 bottom
R4665  0_5%_2  [RSC_100X050X040_2]  95.04 40.79 0 top
R4666  0_5%_2  [RSC_100X050X040_2]  95.04 39.88 0 top
R4667  0_5%_2  [RSC_100X050X040_2]  95.04 38.96 0 top
R4668  0_5%_2  [RSC_100X050X040_2]  95.04 38.05 0 top
R4669  0_5%_2  [RSC_100X050X040_2]  95.04 36.22 0 top
R4670  100K_5%_2  [RSC_100X050X040_2]  111.15 108.46 270 bottom
R4671  10K_5%_2  [RSC_100X050X040_2]  70.42 74.89 180 top
R4672  0_5%_2  [RSC_100X050X040_2]  95.04 35.31 0 top
R4673  0_5%_2  [RSC_100X050X040_2]  95.04 34.39 0 top
R4674  0_5%_2  [RSC_100X050X040_2]  95.04 33.48 0 top
R4676  45.3_1%_2  [RSC_100X050X040_2]  72.43 85.27 0 top
R4677  10K_5%_2  [RSC_100X050X040_2]  68.4 73.51 90 top
R4680  100K_5%_2  [RSC_100X050X040_2]  110.13 103.68 90 bottom
R4681  2.2K_5%_2  [RSC_100X050X040_2]  106.45 57.73 270 bottom
R4682  2.2K_5%_2  [RSC_100X050X040_2]  106.42 54.38 90 bottom
R4683  2.2K_5%_2  [RSC_100X050X040_2]  109.85 57.23 270 bottom
R4684  2.2K_5%_2  [RSC_100X050X040_2]  109.85 55.6 90 bottom
R4686  10K_5%_2  [RSC_100X050X040_2]  106.88 59.03 0 bottom
R4693  10K_1%_2_DY  [RSC_100X050X040_2]  64.65 91.61 270 top
R4698  100_1%_2  [RSC_100X050X040_2]  70.79 97.59 90 top
R4699  100_1%_2  [RSC_100X050X040_2]  101.8 62.66 180 bottom
R4700  100_1%_2  [RSC_100X050X040_2]  70.79 99.24 270 top
R4701  100_1%_2  [RSC_100X050X040_2]  100.17 63.37 0 bottom
R4702  100K_5%_2  [RSC_100X050X040_2]  74.72 41.33 180 bottom
R4705  100K_5%_2  [RSC_100X050X040_2]  70.74 91.54 90 top
R4706  100K_5%_2  [RSC_100X050X040_2]  69.85 91.8 90 top
R4707  100K_5%_2  [RSC_100X050X040_2]  68.96 91.8 90 top
R4708  short_0603_25  [RSC_160X080X080_2_25_SHORT]  77.04 64.26 0 bottom
R4709  10K_5%_2_DY  [RSC_100X050X040_2]  65.83 64.77 90 top
R4711  150_1%_2  [RSC_100X050X040_2]  72.21 91.03 90 top
R4712  80.6_1%_2  [RSC_100X050X040_2]  72.61 72.79 0 top
R4726  100_1%_2  [RSC_100X050X040_2]  67.45 80.13 180 top
R4805  10_5%_2  [RSC_100X050X040_2]  76.12 45.87 90 bottom
R4806  10_5%_2  [RSC_100X050X040_2]  73.3 52.27 90 bottom
R4807  33_5%_2  [RSC_100X050X040_2]  71.77 39.57 0 bottom
R4809  10_5%_2  [RSC_100X050X040_2]  73.58 68.76 90 top
R4810  10_5%_2_DY  [RSC_100X050X040_2]  77.7 66.57 90 top
R4811  10_5%_2  [RSC_100X050X040_2]  73.25 66.57 90 top
R4814  0_5%_2_DY  [RSC_100X050X040_2]  81.28 75.72 90 top
R4815  100K_5%_2  [RSC_100X050X040_2]  65.83 66.4 270 top
R4820  10K_5%_2  [RSC_100X050X040_2]  74.72 77.42 90 top
R4828  5.1_5%_2  [RSC_100X050X040_2]  77.16 52.3 90 bottom
R4834  10K_5%_2  [RSC_100X050X040_2]  115.62 112.12 90 bottom
R4835  short_0402_15  [RSC_100X050X040_2_15_SHORT]  76.6 67.64 270 top
R4836  RSC_0402_DY  [RSC_100X050X040_2]  66.2 80.46 90 top
R4837  0_5%_2  [RSC_100X050X040_2]  77.39 91.41 90 top
R4843  100K_5%_2  [RSC_100X050X040_2]  78.33 68.07 0 top
R4844  4.7K_5%_2_DY  [RSC_100X050X040_2]  73.15 107.14 90 bottom
R4846  0_5%_2  [RSC_100X050X040_2]  76.6 102.54 0 top
R4847  0_5%_2  [RSC_100X050X040_2]  76.48 102.54 0 bottom
R4849  10K_5%_2_DY  [RSC_100X050X040_2]  72.39 103.15 180 top
R4850  200_1%_2  [RSC_100X050X040_2]  74.09 100.08 180 top
R4851  4.7K_5%_2  [RSC_100X050X040_2]  72.39 104.04 0 top
R4892  1K_5%_2_DY  [RSC_100X050X040_2]  67.18 61.62 270 bottom
R4893  1K_5%_2_DY  [RSC_100X050X040_2]  67.94 61.62 270 top
R4894  1K_5%_2  [RSC_100X050X040_2]  66.98 61.62 270 top
R4895  1K_5%_2  [RSC_100X050X040_2]  68.07 61.62 270 bottom
R4900  10K_5%_2  [RSC_100X050X040_2]  66.98 63.75 270 bottom
R4901  10K_5%_2  [RSC_100X050X040_2]  67.94 63.75 270 top
R4902  10K_5%_2_DY  [RSC_100X050X040_2]  66.98 63.75 270 top
R4903  10K_5%_2_DY  [RSC_100X050X040_2]  67.94 63.75 270 bottom
R6000  0.02_1%_6  [RSC_320X160X160_4]  61.9 20.01 90 top
R6001  0.02_1%_6  [RSC_320X160X160_4]  83.46 26.14 90 bottom
R6002  20.5K_1%_2  [RSC_100X050X040_2]  59.69 30.68 90 bottom
R6003  3.32K_1%  [RSC_100X050X040_2]  60.58 30.68 90 bottom
R6004  4.3K_5%_2  [RSC_100X050X040_2]  58.24 29.41 90 bottom
R6005  4.3K_5%_2  [RSC_100X050X040_2]  58.24 27.79 90 bottom
R6007  110K_5%_2  [RSC_100X050X040_2]  65.78 29.95 90 bottom
R6008  91K_5%_2  [RSC_100X050X040_2]  64.89 29.95 270 bottom
R6009  4.3K_5%_2  [RSC_100X050X040_2]  66.67 29.95 90 bottom
R6012  10_5%_5  [RSC_200X125X115_2]  59.05 22.58 270 bottom
R6020  4.7_5%_3  [RSC_160X080X080_2]  63.47 22.07 270 bottom
R6050  33_5%_2  [RSC_100X050X040_2]  104.77 25.81 180 bottom
R6051  1K_5%_2  [RSC_100X050X040_2]  104.77 24.89 180 bottom
R6052  33_5%_2  [RSC_100X050X040_2]  104.77 26.72 180 bottom
R6053  220K_5%_2  [RSC_100X050X040_2]  106.42 23.98 0 bottom
R6054  RSC_0402_DY  [RSC_100X050X040_2]  104.77 23.98 0 bottom
R6055  10K_5%_2  [RSC_100X050X040_2]  91.34 27.18 270 bottom
R6115  2.2_5%_3  [RSC_160X080X080_2]  70.66 140.06 270 bottom
R6150  75K_1%_2  [RSC_100X050X040_2]  88.82 141.2 90 bottom
R6151  10K_1%_2  [RSC_100X050X040_2]  89.71 141.2 270 bottom
R6161  short_0402_15  [RSC_100X050X040_2_15_SHORT]  101.01 130.96 270 bottom
R6165  2.2_5%_3  [RSC_160X080X080_2]  88.97 138.05 180 bottom
R6166  RSC_0402_DY  [RSC_100X050X040_2]  87.32 138.2 90 bottom
R6167  short_0402_15  [RSC_100X050X040_2_15_SHORT]  87.55 140.69 180 bottom
R6198  100K_5%_2  [RSC_100X050X040_2]  89.35 139.06 180 bottom
R6610  0.002_1%_6  [RSC_320X160X080_4]  89.38 86.11 0 bottom
R6612  0_5%_2  [RSC_100X050X040_2]  99.21 69.9 90 bottom
R6615  2.2_5%_3  [RSC_160X080X080_2]  97.84 72.97 180 bottom
R6616  1K_1%_2  [RSC_100X050X040_2]  90.65 68.07 180 bottom
R6618  3.3K_1%_2  [RSC_100X050X040_2]  90.55 65.56 180 bottom
R6619  49.9_1%_2  [RSC_100X050X040_2]  90.65 68.96 0 bottom
R6633  4.02K_1%_2  [RSC_100X050X040_2]  91.89 63.88 90 bottom
R6643  short_0402_5  [RSC_100X050X040_2_SHORT]  93.11 73.28 90 bottom
R6645  2.2_5%_3  [RSC_160X080X080_2]  92 73.71 90 bottom
R6646  22.1K_1%_2  [RSC_100X050X040_2]  97.58 66.22 270 bottom
R6647  10_1%_2  [RSC_100X050X040_2]  96.34 65.13 0 bottom
R6649  100K_1%_2  [RSC_100X050X040_2]  96.34 64.24 0 bottom
R6650  0_5%_2  [RSC_100X050X040_2]  99.56 67.74 0 bottom
R6651  100K_1%_2  [RSC_100X050X040_2]  94.74 64.24 180 bottom
R6652  18.7K_1%_2  [RSC_100X050X040_2]  90.55 64.67 0 bottom
R6654  RSC_0402_DY  [RSC_100X050X040_2]  89.23 66.83 270 bottom
R6655  46.4K_1%_2  [RSC_100X050X040_2]  93.14 64.41 180 bottom
R6658  8.25K_1%_2  [RSC_100X050X040_2]  100.1 69.9 270 bottom
R6659  1K_1%_2  [RSC_100X050X040_2]  90.29 70.21 270 bottom
R6660  1K_1%_2  [RSC_100X050X040_2]  96.75 75.26 270 bottom
R6661  100K_1%_NTC  [RSC_100X050X055_2]  96.8 77.55 0 bottom
R6663  short_0402_5  [RSC_100X050X040_2_SHORT]  88.49 70.89 270 bottom
R6665  short_0402_15  [RSC_100X050X040_2_15_SHORT]  99.51 65.71 0 bottom
R6666  short_0402_5  [RSC_100X050X040_2_SHORT]  89.94 71.45 0 bottom
R6710  0.002_1%_6  [RSC_320X160X080_4]  82.29 52.15 0 bottom
R6712  0_5%_2  [RSC_100X050X040_2]  94.61 51.31 270 bottom
R6715  2.2_5%_3  [RSC_160X080X080_2]  99.39 52.91 90 bottom
R6716  1K_1%_2  [RSC_100X050X040_2]  97.08 62.03 90 bottom
R6718  3.3K_1%_2  [RSC_100X050X040_2]  94.54 61.11 90 bottom
R6719  49.9_1%_2  [RSC_100X050X040_2]  97.43 60.65 180 bottom
R6733  4.02K_1%_2  [RSC_100X050X040_2]  92.83 60.73 0 bottom
R6743  short_0402_5  [RSC_100X050X040_2_SHORT]  101.34 57.43 270 bottom
R6745  2.2_5%_3  [RSC_160X080X080_2]  101.55 59.41 90 bottom
R6746  34.8K_1%_2  [RSC_100X050X040_2]  93.16 54.86 270 bottom
R6747  10_1%_2  [RSC_100X050X040_2]  90.65 55.22 180 bottom
R6749  100K_1%_2  [RSC_100X050X040_2]  91.26 56.11 180 bottom
R6750  48.7K_1%_2  [RSC_100X050X040_2]  94.61 53.39 270 bottom
R6751  100K_1%_2  [RSC_100X050X040_2]  90.88 57.35 90 bottom
R6752  18.7K_1%_2  [RSC_100X050X040_2]  94.54 59.46 270 bottom
R6754  RSC_0402_DY  [RSC_100X050X040_2]  95.81 62.48 180 bottom
R6755  36.5K_1%_2  [RSC_100X050X040_2]  92.15 58.95 90 bottom
R6758  8.25K_1%_2  [RSC_100X050X040_2]  95.88 50.9 0 bottom
R6759  1K_1%_2  [RSC_100X050X040_2]  99.26 62.46 180 bottom
R6760  1K_1%_2  [RSC_100X050X040_2]  100.43 52.25 90 bottom
R6761  100K_1%_NTC  [RSC_100X050X055_2]  83.99 41.68 270 bottom
R6763  short_0402_5  [RSC_100X050X040_2_SHORT]  100.53 61.98 270 bottom
R6765  short_0402_15  [RSC_100X050X040_2_15_SHORT]  93.34 52.45 180 bottom
R6766  short_0402_5  [RSC_100X050X040_2_SHORT]  101.44 61.39 270 bottom
R7000  10K_5%_2  [RSC_100X050X040_2]  88.74 141.07 0 top
R7003  short_0402_5  [RSC_100X050X040_2_SHORT]  90.22 147.04 180 bottom
R7100  10K_5%_2  [RSC_100X050X040_2]  98.6 145.03 180 bottom
R7104  100K_5%_2_DY  [RSC_100X050X040_2]  100.5 145.67 90 bottom
R7109  200_5%_2  [RSC_100X050X040_2]  112.72 118.21 270 bottom
R7110  short_0402_5  [RSC_100X050X040_2_SHORT]  63.78 129.97 0 top
R7111  short_0402_5  [RSC_100X050X040_2_SHORT]  65.02 130.33 270 top
R7112  short_0402_5  [RSC_100X050X040_2_SHORT]  102.66 125.2 180 bottom
R7115  short_0402_5  [RSC_100X050X040_2_SHORT]  102.66 127.86 180 bottom
R7125  200_5%_2  [RSC_100X050X040_2]  101.87 147.16 180 bottom
R7204  short_0402_5  [RSC_100X050X040_2_SHORT]  102.23 57.43 270 bottom
R7206  short_0402_5  [RSC_100X050X040_2_SHORT]  77.72 137.06 0 top
R7207  56.2K_1%_2  [RSC_100X050X040_2]  35.99 35.15 270 bottom
R7208  short_0402_5  [RSC_100X050X040_2_SHORT]  35.53 28.24 0 bottom
R7229  10K_5%_2  [RSC_100X050X040_2]  37.18 37.29 0 bottom
R7230  10K_5%_2  [RSC_100X050X040_2]  79.35 137.06 0 top
R7241  short_0402_5  [RSC_100X050X040_2_SHORT]  96.69 140.06 0 bottom
R7243  short_0402_5  [RSC_100X050X040_2_SHORT]  79.22 67.16 180 top
R7245  10K_5%_2  [RSC_100X050X040_2]  102.05 54.2 270 bottom
R7246  100K_1%_2  [RSC_100X050X040_2]  67.18 35.05 90 bottom
R7247  10K_5%_2  [RSC_100X050X040_2]  64.49 36.35 180 bottom
R7250  short_0402_5  [RSC_100X050X040_2_SHORT]  102.64 55.8 90 bottom
R7252  short_0402_5  [RSC_100X050X040_2_SHORT]  88.69 116.81 0 top
R7256  0_5%_2_DY  [RSC_100X050X040_2]  76.43 107.9 90 bottom
R7501  0_5%_2  [RSC_100X050X040_2]  14.12 124.15 0 top
R7502  0_5%_2  [RSC_100X050X040_2]  14.12 123.24 0 top
R7600  4.7_5%_3  [RSC_160X080X080_2]  82.24 32 0 bottom
R7661  RSC_0603_DY  [RSC_160X080X080_2]  92.4 76.81 270 bottom
R7761  RSC_0603_DY  [RSC_160X080X080_2]  81.68 41.6 180 bottom
R9121  150_5%_2  [RSC_100X050X040_2]  53.86 1.66 0 top
R9122  470_5%_2  [RSC_100X050X040_2]  53.86 2.57 0 top
R9123  150_5%_2  [RSC_100X050X040_2]  58.55 3.33 180 top
R9124  100_5%_2  [RSC_100X050X040_2]  58.56 2.41 180 top
R60000  100K_5%_2  [RSC_100X050X040_2]  88.69 114.15 0 top
R60001  10K_5%_2_DY  [RSC_100X050X040_2]  106.02 109.96 180 bottom
R60002  short_0402_5  [RSC_100X050X040_2_SHORT]  88.69 115.93 0 top
R60003  0_5%_2_DY  [RSC_100X050X040_2]  88.69 115.04 0 top
R60017  470K_5%_2  [RSC_100X050X040_2]  53.62 21.01 180 bottom
R60018  470K_5%_2  [RSC_100X050X040_2]  53.62 21.92 0 bottom
R60019  1M_5%_2  [RSC_100X050X040_2]  57.32 26.54 270 bottom
R60020  3M_5%_2  [RSC_100X050X040_2]  57.32 28.17 270 bottom
R60021  4.7K_5%_3  [RSC_160X080X080_2]  53.21 31.14 270 bottom
R60022  200_5%_2  [RSC_100X050X040_2]  54.86 25.81 180 bottom
R60023  14K_1%_2  [RSC_100X050X040_2]  52.88 27.51 90 bottom
R60024  10K_1%_2  [RSC_100X050X040_2]  52.88 29.13 90 bottom
R60300  8.2K_1%_2  [RSC_100X050X040_2]  37.79 25.55 270 bottom
R60301  10K_1%_2  [RSC_100X050X040_2]  37.23 26.8 180 bottom
R60305  6.04K_1%_1/16W_2  [RSC_100X050X040_2]  38.33 29.69 90 bottom
R60306  511K_1%_2  [RSC_100X050X040_2]  37.84 28.3 180 bottom
R60309  short_0402_15  [RSC_100X050X040_2_15_SHORT]  36.5 29.69 270 bottom
R60315  0_5%_3  [RSC_160X080X055_2]  43.96 21.82 270 bottom
R60316  RSC_0603_DY  [RSC_160X080X080_2]  50.87 24.51 90 bottom
R60359  short_0402_15  [RSC_100X050X040_2_15_SHORT]  37.87 32.84 270 bottom
S1  -  [SCREW260_550_1P]  9.77 143.85 180 bottom
S2  -  [SCREW260_800_700_1P]  68.97 16.95 0 top
S3  -  [SCREW260_1000_800_1P]  114.98 46.25 180 bottom
S4  -  [SCREW260_550_1P]  9.77 87.45 180 bottom
S6  -  [SCREW260_1000_600_1P]  114.98 24.95 180 bottom
S7  -  [SCREW300_1000_700_1P]  12.77 64.75 180 bottom
S10  -  [SCREW260_700_1P]  3 153.05 180 bottom
S9100  -  [SCREW260_700_600_1P]  54.27 7.25 0 top
ST1  STANDOFF_3.1_5.5  [STD_R_FF40005_D30015_M20020_SN]  80.41 58.12 0 bottom
ST2  STANDOFF_3.1_5.5  [STD_R_FF40005_D30015_M20020_SN]  82.09 97.91 0 bottom
ST3  STANDOFF_3.1_5.5  [STD_R_FF40005_D30015_M20020_SN]  44.92 87.81 90 bottom
SW500  DIP_TMG_533_Q_T_R_6P  [SWCH-TACT_DIP_6_SMD_V_150]  36.68 19.23 270 bottom
SW9100  DIP_TMG_533_Q_T_R_6P  [SWCH-TACT_DIP_6_SMD_V_150]  43.2 3.6 270 bottom
TP300  -  [TP24]  68.9 154.51 0 top
TP301  -  [TP24]  68.5 157.4 0 top
TP302  -  [TP24]  67.83 153.83 90 top
TP303  -  [TP24]  82.34 147.45 90 top
TP304  -  [TP24]  63.8 150.85 90 bottom
TP305  -  [TP24]  87.63 157.56 0 top
TP306  -  [TP24]  69.24 165.1 90 top
TP307  -  [TP24]  74.14 146.09 90 top
TP308  -  [TP24]  68.58 158.67 90 top
TP309  -  [TP24]  78.41 146.63 90 top
TP310  -  [TP24]  82.32 146.18 90 top
TP311  -  [TP24]  66.83 154.62 90 top
TP327  -  [TP24]  83.61 147.42 270 top
TP329  -  [TP24]  70.51 164.95 90 top
TP3001  -  [TP24]  68.53 150.98 90 bottom
TP3002  -  [TP24]  71.75 150.6 90 bottom
TP3003  -  [TP24]  75.82 151 90 bottom
TP3150  -  [TP24]  13.76 136.85 0 top
TP3151  -  [TP24]  14.63 135.53 0 top
TP3152  -  [TP24]  14.07 140.51 0 top
TP4500  -  [TP24]  48.67 80.15 180 top
TP4501  -  [TP24]  49.4 81.54 180 top
TP4502  -  [TP24]  51.37 81.66 180 top
TP4503  -  [TP24]  50.48 80.01 180 top
TP4504  -  [TP24]  69.06 68.48 90 top
TP4505  -  [TP24]  67.99 60.17 90 top
TP4506  -  [TP24]  69.26 64.31 90 bottom
TP4509  -  [TP24]  75.25 70.69 90 top
TP4510  -  [TP24]  72.69 71.3 90 top
TP4511  -  [TP24]  64.86 89.89 0 top
TP4512  -  [TP24]  67.99 93.57 0 top
TP4513  -  [TP24]  65.9 87.35 0 top
TP4514  -  [TP24]  66.72 93.29 0 top
TP4515  -  [TP24]  69.24 93.24 0 top
TP4516  -  [TP24]  67.26 90.8 0 top
TP4517  -  [TP24]  65.49 88.7 0 top
TP4531  -  [TP24]  69.75 73.71 90 top
TP4533  -  [TP24]  52.83 97.41 90 bottom
TP4534  -  [TP24]  80.73 66.93 90 bottom
TP4535  -  [TP24]  68.81 69.72 90 top
TP4536  -  [TP24]  80.74 73.96 90 bottom
TP4537  -  [TP24]  69.67 64.87 270 top
TP4540  -  [TP24]  64.68 65.09 90 bottom
TP4541  -  [TP24]  65.8 72.65 0 top
TP4542  -  [TP24]  65.83 74.02 0 top
TP4543  -  [TP24]  69.21 71.27 270 top
TP4544  -  [TP24]  67.87 72.06 270 top
TP4551  -  [TP24]  61.93 88.54 0 top
TP4552  -  [TP24]  63.53 90.02 0 top
TP4553  -  [TP24]  62.33 90.58 0 top
TP4554  -  [TP24]  61.86 92.06 0 top
U301  WINB_NPCE985LB1DX_LQFP_128P  [LQFP_1400X1400X160_128_040]  78.24 156.83 0 top
U500  REA_ALC233_VB2_CGT_MQFN_48P  [MQFN_600X600X100_48_040_T1]  11.62 52.99 90 top
U900  REA_RTS5170_GRT_QFN_24P  [QFN_400X400X100_24_050_T8]  19.48 17.3 0 bottom
U2000  GMT_G524B1T11U_SOT23_5P  [TSOT23_290X160X125_5_095]  111.43 99.85 270 bottom
U2406  GMT_G524B1T11U_SOT23_5P  [TSOT23_290X160X125_5_095]  20.93 119.74 90 bottom
U3151  GMT_G5250Q1T73U_SOT23_3P  [SOT23_290X160X145_3_095]  19.55 135.41 90 bottom
U3500  NUVOTON_NPCT650AAAWX_TSSOP_28P_DY  [TSSOP_970X440X120_28_065_P3]  111.3 124.56 270 bottom
U3950  TOSHIBA_THGBMBG8D4KBAIR_FBGA_153P  [DB10ST-6019B1214301-001]  101.68 34.96 270 bottom
U4100  SAMSUNG_K4B4G1646Q_HYK0_FBGA_96P  [IC-DDR3_SAMSG_1330X1000X110_1]  63.17 110.99 0 bottom
U4101  SAMSUNG_K4B4G1646Q_HYK0_FBGA_96P  [IC-DDR3_SAMSG_1330X1000X110_1]  50.12 110.99 0 bottom
U4102  SAMSUNG_K4B4G1646Q_HYK0_FBGA_96P  [IC-DDR3_SAMSG_1330X1000X110_1]  34.22 88.5 90 bottom
U4103  SAMSUNG_K4B4G1646Q_HYK0_FBGA_96P  [IC-DDR3_SAMSG_1330X1000X110_1]  34.22 101.55 90 bottom
U4104  SAMSUNG_K4B4G1646Q_HYK0_FBGA_96P  [IC-DDR3_SAMSG_1330X1000X110_1]  62.66 50.55 180 bottom
U4105  SAMSUNG_K4B4G1646Q_HYK0_FBGA_96P  [IC-DDR3_SAMSG_1330X1000X110_1]  49.61 50.55 180 bottom
U4106  SAMSUNG_K4B4G1646Q_HYK0_FBGA_96P  [IC-DDR3_SAMSG_1330X1000X110_1]  34.22 60.97 90 bottom
U4107  SAMSUNG_K4B4G1646Q_HYK0_FBGA_96P  [IC-DDR3_SAMSG_1330X1000X110_1]  34.22 74.02 90 bottom
U4441  GMT_AT9667_MSOP8_8P  [MSOP_300X300X110_8_065_T2]  78.74 109.47 180 bottom
U4500  CPU_540276_BGA_1170P  [CPU_INT_BDW_1C_B_270X250]  65.59 81.28 270 bottom
U4502  TI_TCA9406DCUR_VSSOP_8P_DY  [VSSOP_200X230X090_8_050_P2]  106.19 49.91 180 bottom
U4503  TI_TCA9406DCUR_VSSOP_8P  [VSSOP_200X230X090_8_050_P2]  108.08 56.37 180 bottom
U4504  TSB_TC7SZ07FU_SSOP_5P  [SSOP_200X125X100_5_065]  27.94 123.42 0 bottom
U4701  MXIC_MX25U6435FM2I_10G_SOP_8P  [SOP_523X528X216_8_127]  72.89 46.84 180 bottom
U4702  TI_TS3USB221ARSER_QFN_10P  [QFN_200X150X060_10_050]  74.12 39.16 90 bottom
U4703  TC7SZ08FU  [SSOP_200X125X100_5_065]  110.94 115.82 180 bottom
U6000  TI_BQ24725ARGRR_QFN_20P  [QFN_350X350X100_20_050_T1]  62.3 26.74 90 bottom
U6100  MPS_NB670GQ_QFN_16P  [QFN_300X300X100_14_040_T2]  73.96 140.06 270 bottom
U6150  MPS_NB671LGQ_QFN_16P  [QFN_300X300X100_14_040_T1]  93.27 140.06 270 bottom
U6600  ON_NCP81201_QFN_28P  [QFN_400X400X100_28_040_T6]  94.93 69.93 0 bottom
U6700  ON_NCP81201_QFN_28P  [QFN_400X400X100_28_040_T6]  96.65 56.45 270 bottom
U7100  ANPEC_APL3523A_TDFN_14P  [TDFN_300X200X080_14_040_T1]  90.65 126.47 270 bottom
U7102  ANPEC_APL3523A_TDFN_14P  [TDFN_300X200X080_14_040_T1]  64.82 126.11 0 bottom
U9150  MH251EST_MH251EST_TSOT23_3P  [IC-HALL_MST_3_SMD_V_080]  48.97 8.4 180 bottom
U60300  GMT_G5388K11U_QFN_32P  [TQFN_400X400X080_32_040_T1]  42.02 26.71 90 bottom
U60600  RICHTEK_RT5041AGQW_WQFN_28P  [WQFN_400X400X080_28_040_T2]  98.6 115.54 0 bottom
X4500  XTAL_4PIN_19.2MHZ  [XTAL_320X250X090_4_220-3]  88.21 75.18 270 bottom
X4501  32.768KHZ_12.5PF  [XTAL_670X140X140_4_630]  86.2 66.93 270 bottom

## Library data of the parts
B500 = PASSWORD_0805: part number: PASSWORD_0805-PASSWORD_0805,PASSWORD_0805,PASSWORD_0805,0.127MM,PASSWORD_0805,PASSWORD_0805; room: Sheet38
